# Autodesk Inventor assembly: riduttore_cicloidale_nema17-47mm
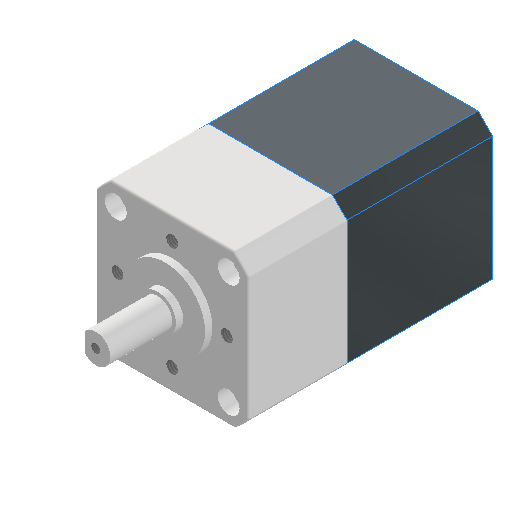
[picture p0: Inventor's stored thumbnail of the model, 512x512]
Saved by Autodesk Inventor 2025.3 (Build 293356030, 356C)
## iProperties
Created: 2026-03
Part Number: riduttore_cicloidale_nema17-47mm
Document SubType Name: Assembly
Designer: R5800u
Author: R5800u
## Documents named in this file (3)
- C:\Users\R5800u\Desktop\robot_riduttore_cicloidale3\Workgroups\NotInProject\riduttore_cicloidale_nema17-47mm.iam
- C:\Users\R5800u\Desktop\robot_riduttore_cicloidale3\Workgroups\NotInProject\NEMA 17.ipt
- C:\Users\R5800u\Desktop\robot_riduttore_cicloidale3\Workgroups\NotInProject\riduttore ciccloidale TS42 15-1.ipt
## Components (2 placed, 2 different names)
1. NEMA 17:1 — Coincidente:1, Coincidente:2, Angolo:1
2. riduttore ciccloidale TS42 15-1:1 — Coincidente:1, Coincidente:2, Angolo:1
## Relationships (3: Mate 2, Angle 1)
- Coincidente:1 [Mate]: NEMA 17:1 ↔ riduttore ciccloidale TS42 15-1:1
- Coincidente:2 [Mate]: NEMA 17:1 ↔ riduttore ciccloidale TS42 15-1:1
- Angolo:1 [Angle]: NEMA 17:1 ↔ riduttore ciccloidale TS42 15-1:1
